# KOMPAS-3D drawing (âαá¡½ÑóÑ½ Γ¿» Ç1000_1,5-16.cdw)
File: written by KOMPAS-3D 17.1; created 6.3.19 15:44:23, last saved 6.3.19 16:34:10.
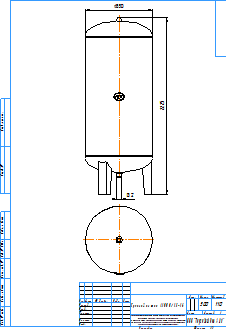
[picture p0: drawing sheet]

Sheet 1: A3, portrait

Title block, sheet 1: name: Гранлевел тип А1000/1,5-16; material: Сталь 10  ГОСТ 1050-88; mass: 500; sheets: 1; sheet format: A3; stored path: C:\Users\kka\KOMPAS_Work\!Trash\ГРАНЛЕВЕЛ тип А Расширительный бак\KOMPAS 2D\Гранлевел тип А1000_1,5-16.cdw

Views: Вид 1, Проекционный вид 2
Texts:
  kka
  adl
  Рама для чертежей
  Лит-Масса-Масштаб
  Материал-Предприятие
  Масштаб
  Изм.
  Лист
  № докум.
  Подп.
  Дата
  Лит.
  Разраб.
  Пров.
  Т.контр.
  Листов
  Внимание! Данный продукт является объектом авторского права ООО «Торговый Дом АДЛ».
  Запрещается изменение, копирование, распространение
  (в том числе путем копирования на другие сайты и ресурсы в Интернете)
  или любое иное использование информации и объектов без предварительного
  согласия правообладателя (ООО «Торговый Дом АДЛ»).
  Н.контр.
  Утв.
  ООО "Торговый дом АДЛ"
  Изменение
  Номер документа
  Подпись
  Обозначение документа
  Наименование изделия
  Масса изделия по ГОСТ 2.109-73
  Порядковый номер листа
  Общее количество листов в документе
  Характер работы, выполненной лицом, подписавшим документ
  Наименование или индекс предприятия, выпускающего документ
  Инв. № подл.
  Подп. и дата
  Взам. инв. №
  Инв. № дубл.
  Инвентарный номер подлинника по ГОСТ 2.501-68
  Подпись принявшего подлинник в отдел технической документации
  Инвентарный номер подлинника, взамен которого выпущен данный подлинник
  Инвентарный номер дубликата по ГОСТ 2.502-68
  Подпись принявшего дубликат в отдел технической документации
  Справ. №
  Перв. примен.
  Обозначение документа, взамен или на основании которого выпущен данный документ
  Обозначение документа, в котором впервые записан данный документ
  Подпись лица, копировавшего чертеж
  Обозначение формата листа
  !Рама для чертежа
Dimensions and other numbers on the sheet: 2225; 850; 2; 1:10; 1; 500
